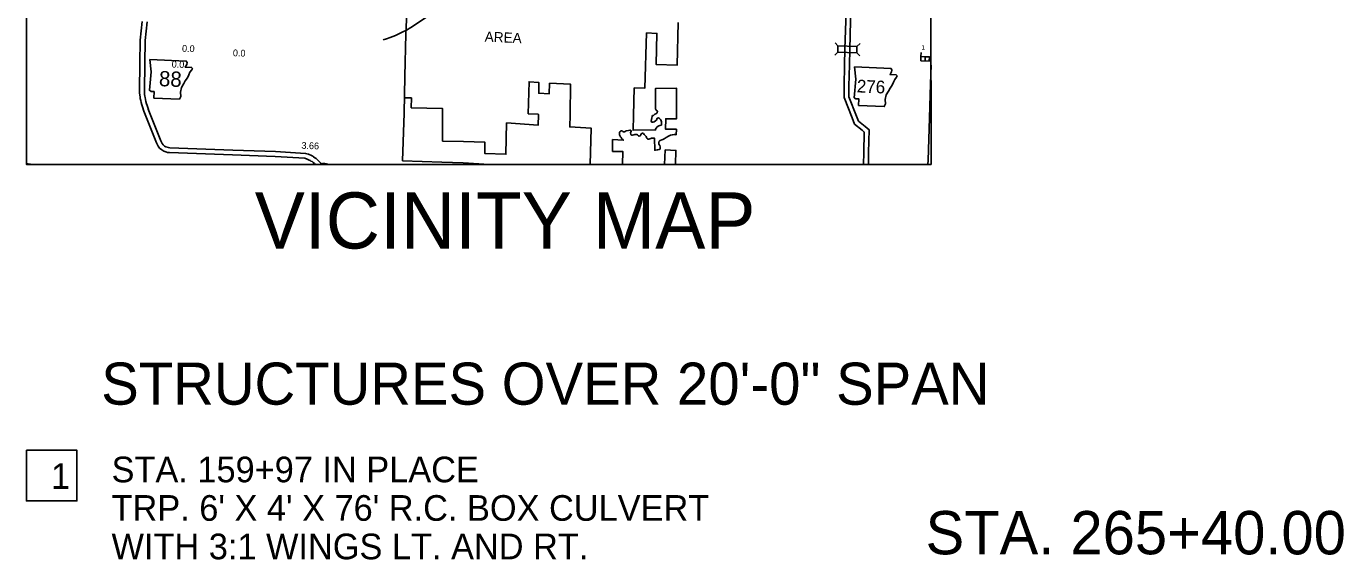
# Model space of a CAD drawing. Extents: x 1196286 to 1268366, y 2040822 to 2082115.
# Drawn here: x 1196286 to 1212706, y 2064593 to 2071244 of the extents above; entities that cross this region are included whole.
import ezdxf

# ---------------------------------------------------------------- set-up
doc = ezdxf.new("R2010")
doc.units = 0
for name, color, linetype in [('10', 7, 'Continuous'), ('55', 7, 'Continuous'), ('60', 7, 'Continuous'), ('Default', 7, 'Continuous'), ('Level 70', 7, 'Continuous'), ('Level 78', 7, 'Continuous'), ('Level 8', 7, 'Continuous'), ('Level 82', 7, 'Continuous'), ('Level 85', 7, 'Continuous'), ('Level 87', 7, 'Continuous'), ('Level 93', 7, 'Continuous'), ('Level 95', 7, 'Continuous'), ('Level 96', 7, 'Continuous'), ('Level 97', 7, 'Continuous'), ('Level 98', 7, 'Continuous')]:
    doc.layers.add(name, color=color, linetype=linetype)

msp = doc.modelspace()

# ---------------------------------------------------------------- linework, layer by layer
at = {"layer": '10'}
msp.add_lwpolyline([(1201362, 2071417), (1201077, 2071228), (1201025, 2071198), (1200971, 2071170), (1200886, 2071131), (1200820, 2071104), (1200774, 2071089), (1200733, 2071075)], dxfattribs=at)
at = {"layer": '55'}
for points in [[(1200995, 2070159), (1201004, 2070617), (1201018, 2071150), (1201040, 2071683), (1201057, 2072261), (1201070, 2072764), (1201087, 2073296), (1201108, 2073821), (1201127, 2074347), (1201141, 2074715)], [(1200995, 2070159), (1201004, 2070617), (1201018, 2071150), (1201040, 2071683), (1201057, 2072261), (1201070, 2072764), (1201087, 2073296), (1201108, 2073821), (1201127, 2074347), (1201141, 2074715)], [(1202055, 2069523), (1201730, 2069543), (1201463, 2069548), (1200975, 2069567), (1200995, 2070159)], [(1202055, 2069523), (1201730, 2069543), (1201463, 2069548), (1200975, 2069567), (1200995, 2070159)]]:
    msp.add_lwpolyline(points, dxfattribs=at)
at = {"layer": 'Default'}
msp.add_lwpolyline([(1196286, 2065957), (1196917, 2065957), (1196917, 2065326), (1196286, 2065326)], close=True, dxfattribs=at)
at = {"layer": 'Level 70'}
for points in [[(1204412, 2071290), (1204399, 2070761), (1204137, 2070767), (1204145, 2071156), (1204017, 2071162), (1203994, 2070471), (1203863, 2070475)], [(1202668, 2070142), (1202664, 2070147), (1202543, 2070153), (1202552, 2070552), (1202676, 2070543), (1202673, 2070410), (1202804, 2070403), (1202809, 2070535), (1203070, 2070521), (1203064, 2070139)], [(1203863, 2070475), (1203852, 2070130)], [(1204092, 2070131), (1204104, 2070132), (1204121, 2070147), (1204141, 2070157), (1204150, 2070164), (1204152, 2070185), (1204138, 2070199), (1204127, 2070215), (1204128, 2070467), (1204391, 2070472), (1204391, 2070127)], [(1200997, 2070353), (1201085, 2070352), (1201083, 2070229), (1201474, 2070218), (1201473, 2069812)], [(1202668, 2070142), (1202666, 2070013), (1202271, 2070040), (1202263, 2069648), (1202000, 2069659), (1201999, 2069800), (1201735, 2069806), (1201473, 2069812)], [(1203315, 2069523), (1203325, 2069976), (1203060, 2069990), (1203064, 2070139)], [(1204092, 2070131), (1204087, 2070119), (1204083, 2070104), (1204078, 2070082), (1204076, 2070062), (1204083, 2070048), (1204096, 2070047), (1204111, 2070054), (1204129, 2070064), (1204142, 2070075), (1204151, 2070097), (1204167, 2070101), (1204179, 2070096), (1204195, 2070076), (1204201, 2070054), (1204202, 2070037), (1204204, 2070022), (1204201, 2070013), (1204182, 2070009), (1204169, 2070003), (1204150, 2069989), (1204135, 2069976), (1204128, 2069962), (1204130, 2069952), (1203848, 2069948), (1203852, 2070130)], [(1204391, 2070127), (1204390, 2070090), (1204257, 2070091), (1204254, 2069960), (1204389, 2069960), (1204387, 2069891), (1204374, 2069894), (1204360, 2069895), (1204337, 2069890), (1204316, 2069886), (1204305, 2069881), (1204289, 2069874), (1204263, 2069859), (1204249, 2069851), (1204235, 2069841), (1204221, 2069833), (1204206, 2069829), (1204188, 2069820), (1204176, 2069811), (1204170, 2069796), (1204170, 2069776), (1204183, 2069756), (1204188, 2069741), (1204188, 2069726), (1204186, 2069719), (1204183, 2069713), (1204172, 2069709), (1204159, 2069704), (1204149, 2069703), (1204129, 2069700), (1204118, 2069699), (1204117, 2069848), (1204104, 2069848), (1204097, 2069848), (1204088, 2069850), (1204077, 2069851), (1204069, 2069847), (1204057, 2069841), (1204045, 2069835), (1204036, 2069836), (1204028, 2069842), (1204021, 2069848), (1204015, 2069859), (1204012, 2069871), (1204007, 2069875), (1204001, 2069881), (1203994, 2069887), (1203986, 2069897), (1203979, 2069906), (1203968, 2069912), (1203962, 2069910), (1203956, 2069907), (1203951, 2069902), (1203945, 2069891), (1203944, 2069886), (1203937, 2069880), (1203924, 2069875), (1203916, 2069878), (1203908, 2069885), (1203903, 2069890), (1203897, 2069894), (1203890, 2069897), (1203883, 2069897), (1203872, 2069896), (1203859, 2069890), (1203843, 2069887), (1203833, 2069888), (1203822, 2069895), (1203817, 2069919), (1203824, 2069933), (1203825, 2069941), (1203817, 2069948), (1203810, 2069949), (1203792, 2069947), (1203762, 2069940), (1203751, 2069934), (1203744, 2069930), (1203730, 2069930), (1203722, 2069933), (1203711, 2069939), (1203704, 2069940), (1203694, 2069937), (1203683, 2069927), (1203681, 2069919), (1203678, 2069912), (1203679, 2069900), (1203680, 2069889), (1203687, 2069875), (1203694, 2069866), (1203700, 2069857), (1203708, 2069843), (1203715, 2069835), (1203726, 2069824), (1203593, 2069831)], [(1203593, 2069831), (1203593, 2069685)], [(1203719, 2069523), (1203723, 2069682), (1203593, 2069685)], [(1204378, 2069523), (1204383, 2069696), (1204249, 2069703), (1204242, 2069523)]]:
    msp.add_lwpolyline(points, dxfattribs=at)
at = {"layer": 'Level 78'}
for points in [[(1197824, 2070830), (1197840, 2070676), (1197820, 2070446), (1197840, 2070433), (1197878, 2070431), (1197875, 2070350), (1198194, 2070336), (1198211, 2070368), (1198208, 2070422), (1198218, 2070482), (1198248, 2070529), (1198267, 2070564), (1198294, 2070601), (1198311, 2070641), (1198325, 2070673), (1198349, 2070700), (1198355, 2070718), (1198346, 2070731), (1198267, 2070734), (1198286, 2070769), (1198290, 2070792), (1198280, 2070810)], [(1206609, 2070737), (1206625, 2070584), (1206605, 2070354), (1206625, 2070340), (1206663, 2070339), (1206659, 2070257), (1206979, 2070244), (1206995, 2070276), (1206993, 2070330), (1207003, 2070390), (1207033, 2070437), (1207052, 2070472), (1207079, 2070509), (1207096, 2070549), (1207110, 2070581), (1207134, 2070608), (1207140, 2070625), (1207130, 2070639), (1207052, 2070642), (1207071, 2070677), (1207075, 2070699), (1207065, 2070717)]]:
    msp.add_lwpolyline(points, close=True, dxfattribs=at)
at = {"layer": 'Level 8'}
msp.add_lwpolyline([(1196286, 2082115), (1207541, 2082115), (1207563, 2069523), (1196286, 2069523)], close=True, dxfattribs=at)
at = {"layer": 'Level 85'}
msp.add_arc((1199995, 2069425), 110, 63.8742, 108.2069, dxfattribs=at)
at = {"layer": 'Level 87'}
for points in [[(1206515, 2071861), (1206507, 2071580), (1206500, 2071312), (1206490, 2070958)], [(1206575, 2071856), (1206567, 2071578), (1206560, 2071311), (1206550, 2070956)], [(1197730, 2071306), (1197706, 2071072), (1197702, 2070782), (1197698, 2070444), (1197698, 2070413), (1197700, 2070386), (1197703, 2070364), (1197706, 2070344), (1197713, 2070317), (1197719, 2070293), (1197726, 2070264), (1197733, 2070239), (1197750, 2070188)], [(1197790, 2071300), (1197766, 2071069), (1197762, 2070781), (1197758, 2070443), (1197758, 2070415), (1197760, 2070392), (1197762, 2070372), (1197765, 2070356), (1197771, 2070332), (1197777, 2070307), (1197784, 2070279), (1197790, 2070257), (1197807, 2070207)], [(1206490, 2070958), (1206485, 2070765), (1206480, 2070497), (1206479, 2070355), (1206579, 2070102)], [(1206550, 2070956), (1206545, 2070764), (1206540, 2070496), (1206539, 2070366), (1206635, 2070124)], [(1207542, 2070100), (1207552, 2070388), (1207560, 2070648), (1207563, 2070758)], [(1199813, 2069577), (1199780, 2069593), (1199765, 2069597), (1199756, 2069600), (1199387, 2069621), (1198857, 2069641), (1198072, 2069671), (1198045, 2069672), (1198024, 2069679), (1197999, 2069686), (1197973, 2069702), (1197947, 2069725), (1197927, 2069749), (1197907, 2069791), (1197750, 2070187)], [(1199839, 2069632), (1199801, 2069649), (1199782, 2069655), (1199766, 2069659), (1199390, 2069681), (1198859, 2069701), (1198075, 2069730), (1198057, 2069731), (1198042, 2069737), (1198023, 2069742), (1198008, 2069751), (1197991, 2069766), (1197978, 2069782), (1197962, 2069815), (1197806, 2070209)], [(1206579, 2070102), (1206610, 2070025), (1206703, 2069948)], [(1206635, 2070124), (1206660, 2070062), (1206742, 2069995)], [(1207524, 2069523), (1207526, 2069573), (1207542, 2070100)], [(1199887, 2069523), (1199877, 2069533), (1199860, 2069546), (1199847, 2069557), (1199834, 2069564), (1199824, 2069571), (1199813, 2069577)], [(1199965, 2069523), (1199955, 2069537), (1199943, 2069551), (1199931, 2069564), (1199917, 2069578), (1199897, 2069594), (1199881, 2069606), (1199866, 2069615), (1199855, 2069623), (1199839, 2069632), (1199837, 2069632)]]:
    msp.add_lwpolyline(points, dxfattribs=at)
at = {"layer": 'Level 93'}
msp.add_lwpolyline([(1196286, 2069533), (1196334, 2069524), (1196341, 2069523)], dxfattribs=at)
at = {"layer": 'Level 95'}
for points in [[(1206742, 2069994), (1206791, 2069954), (1206785, 2069669), (1206782, 2069523)], [(1206704, 2069948), (1206730, 2069926), (1206725, 2069671), (1206722, 2069523)]]:
    msp.add_lwpolyline(points, dxfattribs=at)
at = {"layer": 'Level 96'}
for p, q in [((1207435, 2070814), (1207437, 2070866)), ((1207435, 2070814), (1207563, 2070808)), ((1207563, 2070808), (1207435, 2070814)), ((1207437, 2070866), (1207440, 2070919)), ((1207437, 2070866), (1207437, 2070866)), ((1207437, 2070866), (1207563, 2070861)), ((1207437, 2070866), (1207490, 2070864)), ((1207490, 2070864), (1207488, 2070811)), ((1207490, 2070864), (1207490, 2070864)), ((1207543, 2070862), (1207490, 2070864)), ((1207490, 2070864), (1207490, 2070864)), ((1207543, 2070862), (1207541, 2070809)), ((1207541, 2070809), (1207543, 2070862)), ((1207563, 2070861), (1207543, 2070862)), ((1207543, 2070862), (1207543, 2070862)), ((1207543, 2070862), (1207543, 2070862))]:
    msp.add_line(p, q, dxfattribs=at)
at = {"layer": 'Level 98'}
for p, q in [((1206402, 2071000), (1206366, 2071038)), ((1206640, 2070994), (1206678, 2071030)), ((1206400, 2070920), (1206362, 2070884)), ((1206638, 2070915), (1206674, 2070876))]:
    msp.add_line(p, q, dxfattribs=at)
msp.add_lwpolyline([(1206400, 2070920), (1206638, 2070915), (1206640, 2070994), (1206402, 2071000)], close=True, dxfattribs=at)

# ---------------------------------------------------------------- texts
at = {"layer": '60'}
msp.add_text('VICINITY MAP', height=700, dxfattribs=at).set_placement((1199133, 2068473))
msp.add_text('STA. 265+40.00', height=540, rotation=360, dxfattribs=at).set_placement((1207495, 2064660))
at = {"layer": 'Default'}
for s, height, rotation, p in [('STRUCTURES OVER 20\'-0" SPAN', 525, 359.9958, (1197219, 2066526)), ('STA. 159+97 IN PLACE', 320, 360, (1197348, 2065558)), ('1', 320, 360, (1196593, 2065476)), ("TRP. 6' X 4' X 76' R.C. BOX CULVERT", 320, 360, (1197348, 2065078)), ('WITH 3:1 WINGS LT. AND RT.', 320, 360, (1197348, 2064598))]:
    msp.add_text(s, height=height, rotation=rotation, dxfattribs=at).set_placement(p)
at = {"layer": 'Level 70'}
msp.add_text('AREA', height=126.7, rotation=357.548, dxfattribs=at).set_placement((1201997, 2071053))
at = {"layer": 'Level 78'}
for s, height, p in [('88', 190.1, (1197936, 2070499)), ('276', 158.4, (1206635, 2070421))]:
    msp.add_text(s, height=height, rotation=357.548, dxfattribs=at).set_placement(p)
at = {"layer": 'Level 82'}
msp.add_text('3.66', height=84.5, rotation=357.548, dxfattribs=at).set_placement((1199713, 2069718))
at = {"layer": 'Level 96'}
msp.add_text('1', height=55, rotation=357.548, dxfattribs=at).set_placement((1207443, 2070955))
at = {"layer": 'Level 97'}
for p in [(1198225, 2070928), (1198859, 2070872), (1198096, 2070731)]:
    msp.add_text('0.0', height=84.5, rotation=357.548, dxfattribs=at).set_placement(p)

doc.saveas('drawing.dxf')
